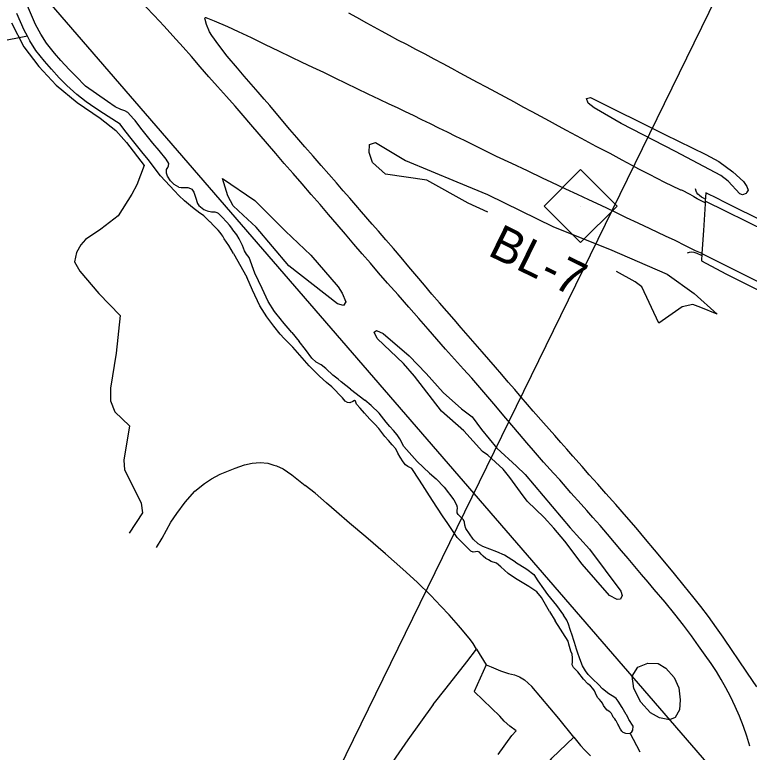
# Model space of a CAD drawing. Extents: x 1517485 to 1521905, y 636528 to 640355.
# Drawn here: x 1519985.4 to 1520407.4, y 637861.7 to 638285.4 of the extents above; entities that cross this region are included whole.
import ezdxf

# ---------------------------------------------------------------- set-up
doc = ezdxf.new("R2010")
doc.units = 0
for name, color, linetype in [('CTL Secondary Horizontal and Vertical CELL', 7, 'Continuous'), ('CTL Secondary Horizontal and Vertical Text', 7, 'Continuous'), ('Exist Hydro Stream or Body of Water', 7, 'Continuous'), ('Exist Right of Way Line', 7, 'Continuous'), ('Exist Roads Curbs', 7, 'Continuous'), ('Exist Roads EOP', 7, 'Continuous'), ('Exist Roads EOP Other', 7, 'Continuous'), ('Exist Roads EOP Text', 7, 'Continuous'), ('Exist Roads Soil', 7, 'Continuous'), ('Exist Structure Major Deck Tunnel Box Culvert', 7, 'Continuous'), ('Exist Vegetation Woods Line', 7, 'Continuous'), ('Scratch_Level_3', 7, 'Continuous')]:
    doc.layers.add(name, color=color, linetype=linetype)

msp = doc.modelspace()

# ---------------------------------------------------------------- linework, layer by layer
at = {"layer": 'CTL Secondary Horizontal and Vertical CELL'}
msp.add_line((1520310.34, 638175.45), (1520310.34, 638175.45), dxfattribs=at)
msp.add_lwpolyline([(1520289.48, 638175.52), (1520310.44, 638196.49), (1520331.44, 638175.48), (1520310.48, 638154.52)], close=True, dxfattribs=at)
at = {"layer": 'Exist Hydro Stream or Body of Water'}
for p, q in [((1519992.68, 638273.03), (1519976.13, 638269.87)), ((1520010.96, 638249.2), (1520015.38, 638244.82)), ((1520026.09, 638244.43), (1520020.42, 638250.22)), ((1520020.98, 638239.52), (1520015.38, 638244.82)), ((1520069.17, 638192.84), (1520062.04, 638202.26)), ((1520069.17, 638192.84), (1520077.12, 638184.25)), ((1520111.1, 638148.24), (1520118.62, 638134.73)), ((1520127.5, 638128.23), (1520123.3, 638136.94)), ((1520144.61, 638102.8), (1520139.16, 638109.11)), ((1520144.61, 638102.8), (1520148.75, 638097.68)), ((1520145.23, 638094.48), (1520140.11, 638099.47)), ((1520167.49, 638071.61), (1520173.77, 638065.31)), ((1520178.25, 638070.27), (1520186.5, 638064.06)), ((1520296.54, 637946.04), (1520300.57, 637940.42)), ((1520292.57, 637942.62), (1520295.95, 637937.23)), ((1520303.3, 637925.49), (1520295.95, 637937.23)), ((1520317.54, 637903.71), (1520314.91, 637906.43)), ((1520314.69, 637901.02), (1520312.14, 637903.65)), ((1520340.6, 637876.64), (1520338.21, 637880.53))]:
    msp.add_line(p, q, dxfattribs=at)
for points in [[(1520020.42, 638250.22), (1520016.58, 638253.99), (1520011.94, 638259.12), (1520008.2, 638263.41), (1520003.62, 638269.13), (1520000.44, 638274.28), (1519997.33, 638279.82), (1519991.48, 638293.15), (1519989.8, 638299.36), (1519987.7, 638305.7)], [(1519992.68, 638273.03), (1519990.72, 638276.52), (1519986.49, 638286.15)], [(1520010.96, 638249.2), (1520006.42, 638254.22), (1520002.54, 638258.67), (1519997.57, 638264.86), (1519994.08, 638270.53), (1519992.68, 638273.03)], [(1520054.5, 638224.64), (1520053.69, 638225.72), (1520050.26, 638229.2), (1520048.57, 638230.2), (1520046.27, 638230.95), (1520043.05, 638232.47), (1520038.61, 638235.65), (1520026.09, 638244.43)], [(1520048.03, 638219.77), (1520045.88, 638222.56), (1520043.86, 638223.95), (1520036.35, 638228.73), (1520031.3, 638231.98), (1520026.48, 638235.34), (1520020.98, 638239.52)], [(1520068.26, 638207.44), (1520064.67, 638211.75), (1520057.79, 638220.26), (1520054.5, 638224.64)], [(1520062.04, 638202.26), (1520058.41, 638206.62), (1520051.4, 638215.28), (1520048.03, 638219.77)], [(1520072.51, 638195.7), (1520072.6, 638196.48), (1520073.24, 638197.66), (1520073.75, 638198.63), (1520073.87, 638199.92), (1520072.34, 638202.54), (1520068.26, 638207.44)], [(1520079.6, 638186.47), (1520076.87, 638187.94), (1520074.92, 638189.95), (1520073.19, 638192.73), (1520072.6, 638194.41), (1520072.51, 638195.7)], [(1520079.6, 638186.47), (1520080.96, 638186.21), (1520084.91, 638186.23), (1520086.31, 638185.69), (1520087.13, 638185.25), (1520088.22, 638183.54), (1520089.26, 638180.58), (1520090.3, 638176.94), (1520091.05, 638175.91), (1520093.96, 638173.53), (1520095.89, 638172.73), (1520098.4, 638172.29), (1520100.3, 638172.13), (1520101.4, 638171.82), (1520102.28, 638171.43)], [(1520097.45, 638166.54), (1520094.1, 638169.84), (1520093.16, 638170.53), (1520091.7, 638171.46), (1520087.51, 638174.66), (1520082.81, 638178.6), (1520079.67, 638181.67), (1520077.12, 638184.25)], [(1520110.68, 638161.87), (1520110.04, 638162.86), (1520108.78, 638164.52), (1520107.3, 638166.31), (1520104.33, 638169.35), (1520102.66, 638171.05), (1520102.28, 638171.43)], [(1520104.9, 638158.15), (1520104.4, 638158.92), (1520103.4, 638160.25), (1520102.19, 638161.71), (1520099.42, 638164.54), (1520097.79, 638166.21), (1520097.45, 638166.54)], [(1520116.13, 638152.93), (1520114.31, 638156.63), (1520112.9, 638158.98), (1520110.68, 638161.87)], [(1520111.1, 638148.24), (1520108.41, 638152.83), (1520105.74, 638156.74), (1520105.08, 638157.87), (1520104.9, 638158.15)], [(1520123.3, 638136.94), (1520120.01, 638145.92), (1520118.46, 638147.82), (1520117.3, 638149.77), (1520116.13, 638152.93)], [(1520140.11, 638099.47), (1520137.91, 638101.91), (1520134.28, 638106.58), (1520130.22, 638111.88), (1520126.21, 638118.13), (1520121.98, 638127.29), (1520118.62, 638134.73)], [(1520139.16, 638109.11), (1520138.56, 638109.89), (1520134.66, 638114.99), (1520130.97, 638120.74), (1520127.5, 638128.23)], [(1520164.38, 638081.95), (1520164.03, 638082.27), (1520161.4, 638084.23), (1520158.52, 638085.89), (1520156.1, 638088.17), (1520152.36, 638093.04), (1520148.75, 638097.68)], [(1520160.5, 638077.72), (1520154.56, 638083.73), (1520149.15, 638089.91), (1520145.23, 638094.48)], [(1520171.12, 638076.06), (1520168.18, 638078.46), (1520164.38, 638081.95)], [(1520167.49, 638071.61), (1520164.43, 638074.12), (1520160.5, 638077.72)], [(1520178.25, 638070.27), (1520172.99, 638074.52), (1520171.13, 638076.05)], [(1520183.74, 638059.44), (1520181.68, 638061.67), (1520181.27, 638062.87), (1520181.07, 638063.52), (1520180.48, 638063.84), (1520179.7, 638063.21), (1520177.92, 638062.45), (1520176.54, 638062.69), (1520175.29, 638063.38), (1520173.77, 638065.31)], [(1520223.72, 638022.01), (1520216.65, 638028.78), (1520208.85, 638037.4), (1520206.65, 638041.8), (1520205.04, 638044.13), (1520202.96, 638046.59), (1520200.81, 638048.91), (1520198.74, 638051.31), (1520194.73, 638056.61), (1520190.19, 638060.88), (1520186.5, 638064.06)], [(1520217.83, 638018.05), (1520213.45, 638024.7), (1520212.35, 638025.29), (1520211.26, 638025.82), (1520209.87, 638026.83), (1520208.57, 638028.67), (1520206.78, 638031.3), (1520205.55, 638033.6), (1520204.23, 638035.97), (1520202.19, 638038.41), (1520200.02, 638040.83), (1520197.98, 638043.18), (1520196.23, 638045.48), (1520194.49, 638047.77), (1520192.23, 638050.3), (1520189.34, 638053.09), (1520186.34, 638056.53), (1520183.74, 638059.44)], [(1520223.72, 638022.01), (1520227.5, 638018.77), (1520232.16, 638014.12), (1520237.56, 638006.75), (1520239.5, 638003.14)], [(1520231.07, 637997.57), (1520225.39, 638006.45), (1520217.83, 638018.05)], [(1520273.09, 637971.01), (1520266.7, 637975), (1520262.31, 637976.95), (1520254.23, 637980.02), (1520251.6, 637981.54), (1520248.68, 637984.24), (1520244.57, 637990.33), (1520243.99, 637992.17), (1520243.86, 637993.93), (1520243.12, 637995.35), (1520241.21, 637997.2), (1520240.09, 637998.33), (1520239.64, 637999.25), (1520239.54, 638000.7), (1520239.75, 638001.97), (1520239.5, 638003.14)], [(1520268.92, 637964.41), (1520264.68, 637968.25), (1520262.19, 637970.37), (1520259.03, 637971.38), (1520257.49, 637972.2), (1520255.96, 637973.07), (1520254.48, 637974.37), (1520253.3, 637975.59), (1520252.34, 637976.6), (1520251.3, 637977.15), (1520250.07, 637976.89), (1520248.69, 637976.73), (1520247.4, 637977.28), (1520239.6, 637985.09), (1520234.11, 637993.16), (1520231.07, 637997.57)], [(1520273.09, 637971.01), (1520279.56, 637966.95), (1520283.53, 637963.83), (1520285.89, 637960.25), (1520289.09, 637955.59), (1520291.39, 637952.32), (1520296.54, 637946.04)], [(1520292.57, 637942.62), (1520288.06, 637950.69), (1520285.32, 637953.88), (1520280.7, 637957.04), (1520273.1, 637961.55), (1520268.92, 637964.41)], [(1520306.44, 637926.44), (1520305.86, 637928.37), (1520304.58, 637932.31), (1520303.56, 637935.39), (1520302.64, 637937.59), (1520300.57, 637940.42)], [(1520305.58, 637918.09), (1520304.94, 637919.89), (1520303.81, 637923.82), (1520303.3, 637925.49)], [(1520308.67, 637919.19), (1520308.07, 637920.89), (1520306.96, 637924.75), (1520306.44, 637926.44)], [(1520314.91, 637906.43), (1520313.24, 637908.6), (1520311.62, 637911.37), (1520310.04, 637915.32), (1520308.67, 637919.19)], [(1520312.14, 637903.65), (1520308.97, 637908.02), (1520306.36, 637910.5), (1520305.69, 637911.91), (1520305.8, 637913.65), (1520305.74, 637915.91), (1520305.58, 637918.09)], [(1520336.67, 637883.48), (1520334.39, 637887.5), (1520332.05, 637891.02), (1520330.85, 637892.63), (1520329.5, 637893.57), (1520326.65, 637895.24), (1520323, 637898.2), (1520320.74, 637900.7), (1520317.54, 637903.71)], [(1520330.81, 637880.04), (1520330.24, 637881.01), (1520329.23, 637881.98), (1520328.72, 637882.81), (1520328.3, 637883.98), (1520327.26, 637885.02), (1520325.8, 637885.88), (1520324.61, 637887.21), (1520323.55, 637888.61), (1520323.1, 637889.86), (1520322.37, 637890.98), (1520321.36, 637891.96), (1520320.38, 637892.97), (1520319.67, 637894.31), (1520319.04, 637895.6), (1520318.53, 637897), (1520317.6, 637898.33), (1520316.1, 637899.82), (1520314.69, 637901.02)], [(1520338.21, 637880.53), (1520337.96, 637881), (1520336.96, 637882.98), (1520336.67, 637883.48)], [(1520332.24, 637877.29), (1520331.93, 637877.86), (1520330.99, 637879.74), (1520330.81, 637880.04)], [(1520334.08, 637873.91), (1520333.32, 637875.08), (1520332.72, 637876.39), (1520332.24, 637877.29)], [(1520334.08, 637873.91), (1520334.7, 637873.26), (1520336.31, 637872.65), (1520338.4, 637872.49), (1520339, 637872.72), (1520339.87, 637873.54), (1520340.4, 637874.5), (1520340.6, 637876.64)], [(1520344.71, 637861.75), (1520339, 637872.72)]]:
    msp.add_lwpolyline(points, dxfattribs=at)
at = {"layer": 'Exist Right of Way Line'}
msp.add_line((1520000.91, 638297.35), (1520402.4, 637833.27), dxfattribs=at)
at = {"layer": 'Exist Roads Curbs'}
for points in [[(1520381.94, 638179.67), (1520380.03, 638180.69), (1520378.73, 638181.51), (1520377.83, 638182.45), (1520377.33, 638183.2), (1520376.92, 638184.16), (1520376.55, 638185.46)], [(1520379.85, 638147.17), (1520377.49, 638148.35), (1520375.73, 638148.94), (1520374.32, 638149.04), (1520372.94, 638148.78), (1520371.77, 638148.38)]]:
    msp.add_lwpolyline(points, dxfattribs=at)
at = {"layer": 'Exist Roads EOP'}
for points in [[(1520407.7, 637865.28), (1520405.99, 637870.96), (1520403.98, 637876.57), (1520401.81, 637882.5), (1520399.35, 637888.11), (1520396.52, 637893.71), (1520393.86, 637898.72), (1520391.25, 637903.61), (1520388.57, 637908.19), (1520385.58, 637912.66), (1520382.02, 637917.56), (1520378.16, 637922.91), (1520374.1, 637928.59), (1520369.52, 637934.74), (1520364.54, 637941.07), (1520359.03, 637947.89), (1520352.83, 637955.32), (1520349.34, 637959.41), (1520345.54, 637963.89), (1520341.63, 637968.5), (1520337.84, 637972.97), (1520334.02, 637977.48), (1520330.02, 637982.21), (1520325.87, 637987.07), (1520321.63, 637991.93), (1520317.6, 637996.53), (1520314.07, 638000.57), (1520310.89, 638004.19), (1520304.94, 638010.86), (1520298.48, 638018.16), (1520294.99, 638022.08), (1520289.25, 638028.44), (1520283.4, 638035.1), (1520279.57, 638039.59), (1520275.41, 638044.5), (1520270.99, 638049.7), (1520266.39, 638055.06), (1520261.73, 638060.5), (1520257.12, 638065.95), (1520252.52, 638071.32), (1520247.91, 638076.57), (1520243.14, 638081.89), (1520238.08, 638087.53), (1520232.94, 638093.28), (1520227.93, 638098.97), (1520222.85, 638104.78), (1520217.49, 638110.93), (1520211.77, 638117.48), (1520205.57, 638124.5), (1520199.57, 638131.3), (1520194.43, 638137.2), (1520189.71, 638142.65), (1520185, 638148.12), (1520180.25, 638153.66), (1520175.41, 638159.3), (1520170.54, 638164.99), (1520165.68, 638170.65), (1520160.76, 638176.37), (1520155.7, 638182.25), (1520150.55, 638188.2), (1520145.37, 638194.16), (1520140.26, 638200.03), (1520135.34, 638205.73), (1520130.53, 638211.33), (1520125.75, 638216.9), (1520121.06, 638222.35), (1520116.54, 638227.58), (1520111.92, 638232.85), (1520106.98, 638238.42), (1520101.91, 638244.13), (1520096.93, 638249.81), (1520091.96, 638255.52), (1520086.94, 638261.35), (1520082.22, 638266.77), (1520078.14, 638271.29), (1520074.53, 638275.22), (1520071.18, 638278.87), (1520065.43, 638285.08), (1520060.69, 638289.94)], [(1520411.82, 637899.28), (1520406.45, 637907.26), (1520400.91, 637915.32), (1520397.97, 637919.67), (1520392.46, 637927.84), (1520388.57, 637933.25), (1520383.87, 637939.71), (1520379.47, 637945.57), (1520375.05, 637951.15), (1520370.03, 637957.31), (1520364.43, 637964.26), (1520358.78, 637971.02), (1520352.89, 637977.97), (1520347.8, 637984.08), (1520342.32, 637990.66), (1520336.8, 637997.06), (1520330.68, 638004.02), (1520325.07, 638010.34), (1520320.35, 638015.67), (1520315.41, 638021.14), (1520311.34, 638025.86), (1520306.05, 638031.93), (1520302.6, 638035.84), (1520299.12, 638039.77), (1520295.69, 638043.63), (1520289.23, 638050.97), (1520283.26, 638057.72), (1520279.96, 638061.51), (1520276.3, 638065.77), (1520272.6, 638070.09), (1520268.92, 638074.42), (1520265.22, 638078.73), (1520261.51, 638083.03), (1520257.73, 638087.38), (1520253.87, 638091.82), (1520249.91, 638096.35), (1520245.85, 638100.98), (1520241.8, 638105.62), (1520237.75, 638110.28), (1520233.62, 638115.07), (1520229.37, 638120), (1520225.08, 638125), (1520220.74, 638130.06), (1520216.32, 638135.27), (1520211.84, 638140.61), (1520207.36, 638145.9), (1520202.92, 638151.09), (1520198.57, 638156.16), (1520194.38, 638161.02), (1520190.79, 638165.15), (1520184.63, 638172.15), (1520181.34, 638175.95), (1520177.85, 638179.97), (1520174.15, 638184.23), (1520170.17, 638188.82), (1520165.91, 638193.76), (1520161.43, 638198.89), (1520156.76, 638204.19), (1520152.03, 638209.56), (1520147.37, 638214.89), (1520143.48, 638219.45), (1520137.52, 638226.63), (1520131.91, 638233.28), (1520128.76, 638236.93), (1520125.2, 638241.02), (1520121.25, 638245.52), (1520117.26, 638250.13), (1520113.37, 638254.67), (1520107.48, 638261.64), (1520102.62, 638268.01), (1520098.66, 638273.49), (1520097.22, 638275.55), (1520095.55, 638279.88), (1520094.73, 638282.7), (1520094.66, 638283.45), (1520094.8, 638283.77), (1520095.12, 638283.81), (1520095.55, 638283.74), (1520096.11, 638283.55), (1520099.88, 638281.93), (1520107.65, 638278.62), (1520113.82, 638275.79), (1520121.13, 638272.34), (1520129.29, 638268.41), (1520136.97, 638264.7), (1520143.97, 638261.33), (1520150.41, 638258.25), (1520156.42, 638255.39), (1520162.69, 638252.37), (1520169.26, 638249.2), (1520175.67, 638246.11), (1520181.91, 638243.13), (1520188.3, 638240.08), (1520194.75, 638237.01), (1520200.38, 638234.33), (1520205.15, 638232.07), (1520209.73, 638229.87), (1520214.26, 638227.66), (1520219, 638225.33), (1520223.96, 638222.88), (1520228.87, 638220.47), (1520233.72, 638218.1), (1520238.6, 638215.72), (1520243.53, 638213.29), (1520248.5, 638210.82), (1520253.45, 638208.35), (1520262.05, 638204.25), (1520270.75, 638200.16), (1520279.7, 638195.92), (1520288.71, 638191.64), (1520293.32, 638189.48), (1520301.89, 638185.48), (1520308.46, 638182.39), (1520315.1, 638179.3), (1520322.17, 638175.98), (1520329.3, 638172.52), (1520336.65, 638168.99), (1520343.4, 638165.85), (1520350.25, 638162.63), (1520359.04, 638158.48), (1520364.63, 638155.89), (1520370.56, 638152.96), (1520375.13, 638150.62), (1520376.39, 638150.04), (1520380.07, 638148.38)], [(1520381.99, 638177.31), (1520377.41, 638179.72), (1520375.6, 638180.76), (1520375.46, 638180.91), (1520375.37, 638181.04), (1520375.17, 638181.2), (1520373.1, 638182.35), (1520369.03, 638184.43), (1520368.45, 638184.64), (1520368.13, 638184.67), (1520367.59, 638184.81), (1520358.82, 638189.08), (1520350.02, 638193.59), (1520343.98, 638196.76), (1520340.09, 638198.87), (1520334.39, 638201.95), (1520327.44, 638205.67), (1520319.48, 638209.8), (1520310.96, 638214.26), (1520302.46, 638218.86), (1520297.77, 638221.45), (1520292.66, 638224.27), (1520287.58, 638227.03), (1520282.58, 638229.71), (1520277.54, 638232.43), (1520272.43, 638235.24), (1520267.15, 638238.09), (1520261.71, 638240.97), (1520256.37, 638243.8), (1520251.17, 638246.57), (1520246.18, 638249.27), (1520241.38, 638251.89), (1520236.51, 638254.53), (1520231.53, 638257.19), (1520226.38, 638259.93), (1520221.08, 638262.74), (1520215.79, 638265.52), (1520210.55, 638268.27), (1520205.54, 638270.92), (1520200.74, 638273.47), (1520196.04, 638275.99), (1520187.62, 638280.58), (1520181.82, 638283.9), (1520177.4, 638286.31)]]:
    msp.add_lwpolyline(points, dxfattribs=at)
at = {"layer": 'Exist Roads EOP Other'}
for points in [[(1520225.76, 637889.22), (1520233.25, 637898.52), (1520245.11, 637913.74), (1520250.62, 637921.01)], [(1520250.62, 637921.01), (1520256.25, 637911.96), (1520249.29, 637896.62)], [(1520264.04, 637882.48), (1520254.58, 637891.6), (1520249.29, 637896.62)], [(1520225.76, 637889.22), (1520211.15, 637868.84), (1520195.24, 637845.97), (1520183.02, 637829.06), (1520222.92, 637796.97)], [(1520263.16, 637860.42), (1520270.96, 637871.36), (1520273.39, 637874), (1520269.87, 637876.78), (1520266.66, 637879.53), (1520264.04, 637882.48)], [(1520282.44, 637846.28), (1520286.65, 637850.16), (1520289.13, 637852.69), (1520291.19, 637854.74), (1520293.99, 637858.34), (1520306.54, 637870.35), (1520310.38, 637865.67), (1520312.99, 637862.99), (1520314.49, 637861.46), (1520315.95, 637859.91), (1520316.25, 637859.78)]]:
    msp.add_lwpolyline(points, dxfattribs=at)
at = {"layer": 'Exist Roads Soil'}
msp.add_line((1520278.28, 637903.28), (1520282.4, 637899.49), dxfattribs=at)
for points in [[(1520066.91, 637979.32), (1520069.99, 637984.79), (1520075.08, 637993.88), (1520078.49, 637998.94), (1520083.32, 638005.42), (1520088.81, 638011.67), (1520094.32, 638016.21), (1520098.42, 638018.79), (1520103.45, 638021.44), (1520112.09, 638025.01), (1520117.33, 638026.91)], [(1520117.33, 638026.91), (1520121.71, 638027.83), (1520126.28, 638028.29), (1520130.77, 638027.74), (1520134.21, 638026.7), (1520135.68, 638026.34), (1520139.55, 638024.5), (1520144.52, 638021.04), (1520152.19, 638014.94)], [(1520208.41, 637966.95), (1520198.34, 637975.69), (1520187.08, 637985.56), (1520177.69, 637993.44), (1520170.14, 637999.88), (1520164.5, 638004.91), (1520157.92, 638010.59), (1520152.19, 638014.94)], [(1520250.62, 637921.01), (1520248.7, 637924.19), (1520247.28, 637926.25), (1520242.68, 637931.85), (1520240.31, 637934.56), (1520234.87, 637940.64), (1520230.2, 637945.66), (1520224.51, 637951.75), (1520216.57, 637959.4), (1520208.41, 637966.95)], [(1520256.25, 637911.96), (1520259.17, 637910.8), (1520264.44, 637908.58), (1520269.07, 637907.06), (1520272.58, 637906.2), (1520275.45, 637905.1), (1520278.28, 637903.28)], [(1520306.54, 637870.35), (1520298, 637881.09), (1520282.4, 637899.49)]]:
    msp.add_lwpolyline(points, dxfattribs=at)
at = {"layer": 'Exist Structure Major Deck Tunnel Box Culvert'}
for points in [[(1520551.82, 638093.57), (1520551.79, 638097.59), (1520542.8, 638102.87), (1520514.84, 638116.88), (1520462.99, 638142.85), (1520418.16, 638165.28), (1520392.4, 638178.2), (1520389.54, 638179.58), (1520382.4, 638183.11), (1520382.11, 638178.37)], [(1520417.78, 638160.63), (1520382.11, 638178.37), (1520382, 638176.72), (1520381.06, 638161.53), (1520380.17, 638148.33), (1520406.27, 638135.2), (1520418.02, 638129.31)], [(1520380.17, 638148.33), (1520379.88, 638143.99), (1520393.93, 638136.59), (1520414.99, 638125.99), (1520445.27, 638110.89), (1520484.97, 638090.98), (1520508.76, 638079.01), (1520537.87, 638064.33), (1520549.6, 638059.06), (1520549.88, 638063.3)]]:
    msp.add_lwpolyline(points, dxfattribs=at)
at = {"layer": 'Exist Vegetation Woods Line'}
for points in [[(1519983.54, 638280.72), (1519990.55, 638267.01), (1519999.15, 638255.78), (1520009.2, 638244.95), (1520021.23, 638234.99), (1520034.37, 638225.94), (1520043.48, 638218.88), (1520049.6, 638212.11), (1520059.65, 638198.84), (1520055.43, 638187.64), (1520052.7, 638182.34), (1520044.71, 638169.88), (1520034.92, 638162.17), (1520026.07, 638156.33), (1520023.27, 638153.16), (1520020.78, 638148.75), (1520019.75, 638143.57), (1520022.71, 638138.11), (1520033.73, 638125.29), (1520045.91, 638112.62), (1520043.58, 638090.93), (1520040.47, 638070.86), (1520040.3, 638063.69), (1520042.97, 638057.33), (1520051.35, 638049.19), (1520048.02, 638029.54), (1520048.4, 638024), (1520054.48, 638011.86), (1520058.08, 638004.75), (1520058.86, 637999.38), (1520051.07, 637987.58)], [(1520401.95, 638182.52), (1520395.21, 638189.74), (1520391.1, 638193.02), (1520364.92, 638206.92), (1520333.84, 638222.96), (1520318.33, 638231.91), (1520314.74, 638234.59), (1520313.85, 638237.36), (1520316.1, 638237.89), (1520358.94, 638216.59), (1520382.44, 638205.17), (1520389.99, 638201.12), (1520398, 638195.21), (1520404.09, 638189.64), (1520405.94, 638186.8), (1520406.66, 638184.65), (1520406.06, 638183.53), (1520405.56, 638182.69), (1520403.49, 638182.05), (1520401.95, 638182.52)], [(1520257.14, 638172.06), (1520245.85, 638177.21), (1520222.12, 638190.49), (1520198.47, 638193.89), (1520191, 638200.47), (1520189.03, 638206.26), (1520189.21, 638210.84), (1520192.66, 638212.09), (1520209.85, 638201.73), (1520239.28, 638189.43), (1520256.95, 638182.18), (1520294.87, 638163.66), (1520327.08, 638150.74), (1520360.14, 638136.39), (1520375.82, 638125.32), (1520388.87, 638113.35)], [(1520104.65, 638191.45), (1520123.37, 638178.72), (1520140.93, 638161.19), (1520155.43, 638147.3), (1520171.19, 638129.2), (1520173.52, 638125.46), (1520175.64, 638120.49), (1520174.34, 638118.33), (1520170.89, 638119.44), (1520142.88, 638141.28), (1520123.99, 638163.35), (1520116.55, 638170.34), (1520110.94, 638175.74), (1520107.8, 638181.36), (1520104.65, 638191.45)], [(1520388.87, 638113.35), (1520379.61, 638117.28), (1520374.92, 638118.9), (1520368.86, 638117.57), (1520355.38, 638108.25), (1520345.69, 638129.17), (1520341.85, 638132.03), (1520331.18, 638137.98)], [(1520311.43, 637969.74), (1520301.43, 637983.01), (1520295.07, 637990.52), (1520289.53, 637996.69), (1520279.84, 638005.94), (1520275.88, 638011.18), (1520269.89, 638019.59), (1520266.02, 638024.4), (1520257.27, 638032.5), (1520254.16, 638034.45), (1520243.39, 638046.35), (1520230.47, 638057.69), (1520214.98, 638077.77), (1520208.74, 638085.03), (1520193.66, 638099.4), (1520191.94, 638103.03), (1520193.13, 638103.96), (1520196.98, 638102.31), (1520211.92, 638089.45), (1520221.73, 638079.37), (1520231.58, 638068.36), (1520241.98, 638059.08), (1520248.12, 638054.38), (1520253.59, 638047.22), (1520262.3, 638036.42), (1520273.61, 638026.16), (1520278.68, 638021.29), (1520304.4, 637990.7), (1520315.63, 637978.48)], [(1520315.63, 637978.48), (1520333.65, 637954.37), (1520334.35, 637951.79), (1520333.49, 637949.65), (1520331.55, 637949.42), (1520326.99, 637951.74), (1520311.43, 637969.74)], [(1520364.76, 637881.63), (1520361.61, 637880.31), (1520355.87, 637881.51), (1520350.59, 637884.42), (1520345.04, 637890.48), (1520341.11, 637898.35), (1520340.17, 637905.42), (1520343.35, 637910.55), (1520349.18, 637912.88), (1520354.98, 637912.67), (1520359.4, 637910.06), (1520364.17, 637904.65), (1520366.97, 637898.76), (1520367.61, 637891.89), (1520367.38, 637886.15), (1520364.76, 637881.63)]]:
    msp.add_lwpolyline(points, dxfattribs=at)
at = {"layer": 'Scratch_Level_3'}
msp.add_line((1520770.84, 639077.45), (1520017.02, 637536.16), dxfattribs=at)

# ---------------------------------------------------------------- texts
at = {"layer": 'CTL Secondary Horizontal and Vertical Text'}
msp.add_text('BL-7', height=20, rotation=333.9377, dxfattribs=at).set_placement((1520256.48, 638147.61))
at = {"layer": 'Exist Roads EOP Text'}
msp.add_text('S HARDING AVE', height=16, rotation=322.6115, dxfattribs=at).set_placement((1519909.06, 637860.2))

doc.saveas('drawing.dxf')
